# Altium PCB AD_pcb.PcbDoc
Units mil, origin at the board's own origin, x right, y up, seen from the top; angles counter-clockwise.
Board outline 6000 x 2330 mil, 2 copper layers (Top Layer, Bottom Layer); 6 components, 0 nets, 323 pads, 0 vias.
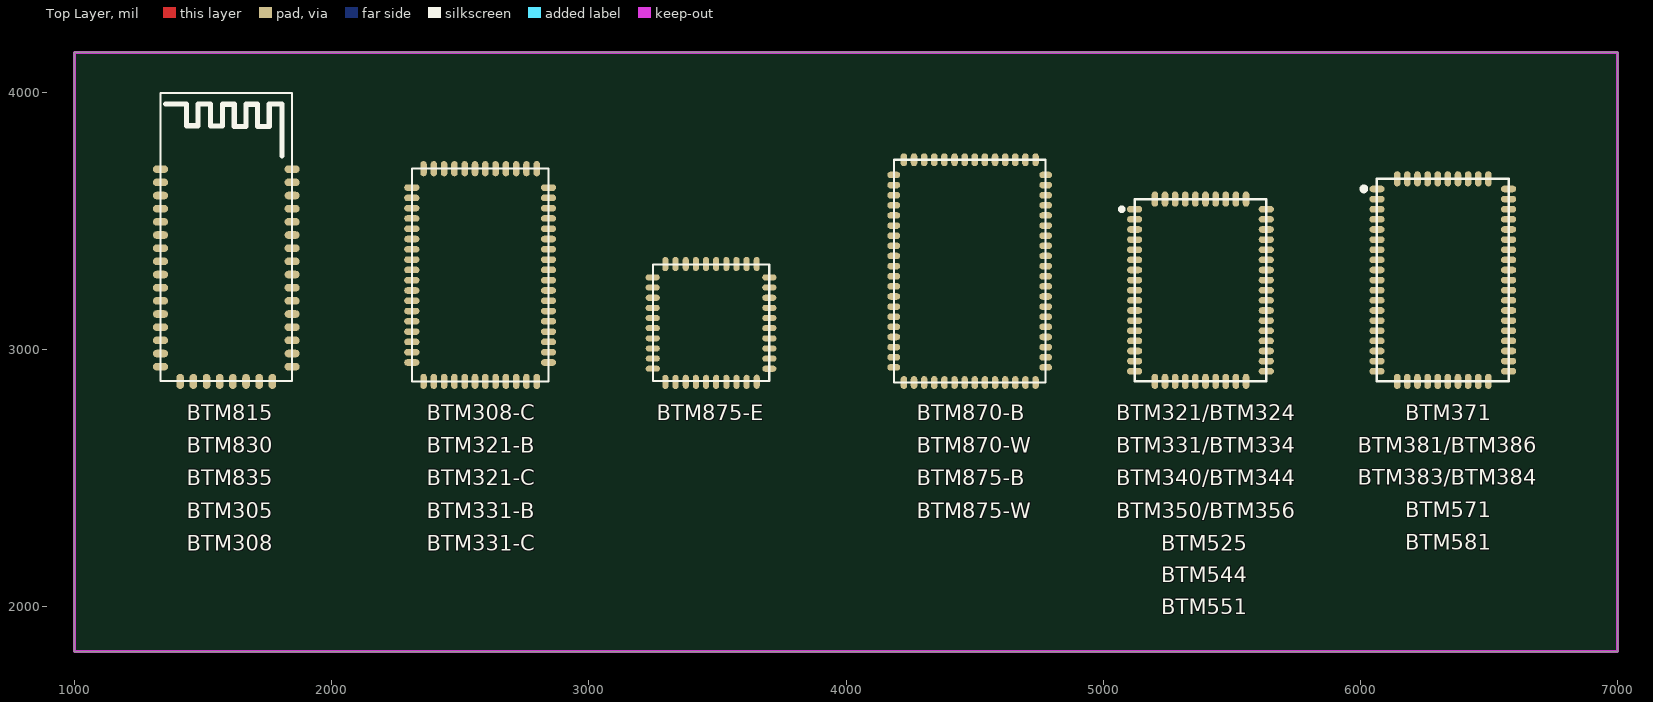
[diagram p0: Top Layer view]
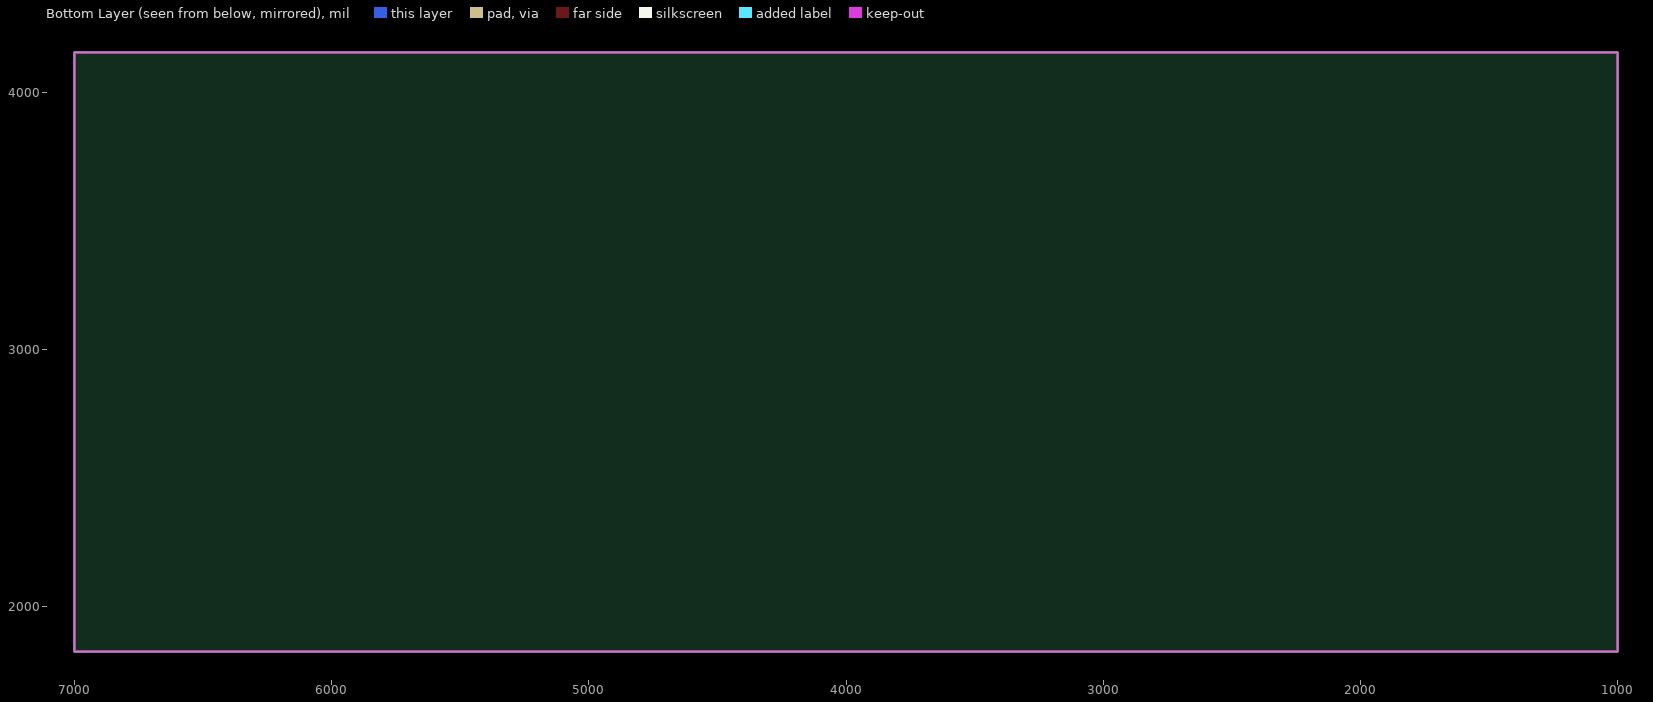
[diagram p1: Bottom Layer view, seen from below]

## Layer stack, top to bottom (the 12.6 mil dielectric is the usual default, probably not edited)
Top Solder: solder mask 0.4, Solder Resist, Dk 3.5
Top Layer: signal copper 1.4
Dielectric 1: dielectric 12.6, FR-4, Dk 4.8
Bottom Layer: signal copper 1.4
Bottom Solder: solder mask 0.4, Solder Resist, Dk 3.5

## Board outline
1000,1825 1000,4155 7000,4155 7000,1825

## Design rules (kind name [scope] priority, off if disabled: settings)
Clearance [All] p1: gap=10
PolygonConnect [All] p1: connectstyle=Relief reliefconductorwidth=10 reliefentries=4 polygonreliefangle="90 Angle" airgapwidth=10
RoutingVias [All] p1: holewidth=28 width=50 viastyle="Through Hole" minholewidth=28 minwidth=50 maxholewidth=28 maxwidth=50
SolderMaskExpansion [All] p1: expansion=4
Width [All] p1: maxlimit=10 minlimit=10 preferedwidth=10
30 further rules are at their usual default settings.

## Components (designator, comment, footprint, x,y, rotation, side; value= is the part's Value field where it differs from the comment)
? "" BTM571 6320,3269.37 r0 top
? "" BTM05F 1590.91,3288.07 r0 top
? "" BTM625-C 2577.74,3289.05 r0 top
? "" BTM875-E 3475.23,3102.89 r0 top
? "" BTM870-B 4480.99,3304.21 r0 top
? "" BTM524 5377.9,3230 r0 top

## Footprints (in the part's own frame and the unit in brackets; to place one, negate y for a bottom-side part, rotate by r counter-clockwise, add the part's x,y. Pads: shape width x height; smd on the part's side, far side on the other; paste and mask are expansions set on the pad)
BTM05F [mm]
  oval 1.5x0.75 smd: 1(-6.5,10.475) 2(-6.5,9.175) 3(-6.5,7.875) 4(-6.5,6.575) 5(-6.5,5.275) 6(-6.5,3.975) 7(-6.5,2.675) 8(-6.5,1.375) 9(-6.5,0.075) 10(-6.5,-1.225) 11(-6.5,-2.525) 12(-6.5,-3.825) 13(-6.5,-5.125) 14(-6.5,-6.425) 15(-6.5,-7.725) 16(-6.5,-9.025) 25(6.5,-9.025) 26(6.5,-7.725) 27(6.5,-6.425) 28(6.5,-5.125) 29(6.5,-3.825) 30(6.5,-2.525) 31(6.5,-1.225) 32(6.5,0.075) 33(6.5,1.375) 34(6.5,2.675) 35(6.5,3.975) 36(6.5,5.275) 37(6.5,6.575) 38(6.5,7.875) 39(6.5,9.175) 40(6.5,10.475)
  oval 0.75x1.5 smd: 17(-4.55,-10.475) 18(-3.25,-10.475) 19(-1.95,-10.475) 20(-0.65,-10.475) 21(0.65,-10.475) 22(1.95,-10.475) 23(3.25,-10.475) 24(4.55,-10.475)
  silkscreen extent -6.51,-10.45 6.49,18, body extent -6.51,-10.45 6.49,18, height 2.6
BTM524 [mm]
  oval 1.5x0.65 smd: 1(-6.5,8) 2(-6.5,7) 3(-6.5,6) 4(-6.5,5) 5(-6.5,4) 6(-6.5,3) 7(-6.5,2) 8(-6.5,1) 9(-6.5,0) 10(-6.5,-1) 11(-6.5,-2) 12(-6.5,-3) 13(-6.5,-4) 14(-6.5,-5) 15(-6.5,-6) 16(-6.5,-7) 17(-6.5,-8) 28(6.5,-8) 29(6.5,-7) 30(6.5,-6) 31(6.5,-5) 32(6.5,-4) 33(6.5,-3) 34(6.5,-2) 35(6.5,-1) 36(6.5,0) 37(6.5,1) 38(6.5,2) 39(6.5,3) 40(6.5,4) 41(6.5,5) 42(6.5,6) 43(6.5,7) 44(6.5,8)
  oval 0.65x1.5 smd: 18(-4.5,-9) 19(-3.5,-9) 20(-2.5,-9) 21(-1.5,-9) 22(-0.5,-9) 23(0.5,-9) 24(1.5,-9) 25(2.5,-9) 26(3.5,-9) 27(4.5,-9) 45(4.5,9) 46(3.5,9) 47(2.5,9) 48(1.5,9) 49(0.5,9) 50(-0.5,9) 51(-1.5,9) 52(-2.5,9) 53(-3.5,9) 54(-4.5,9)
  silkscreen extent -7.9,-9 6.5,9, body extent -6.5,-9 6.5,9, height 2.6
BTM571 [mm]
  oval 1.5x0.65 smd: 1(-6.5,9) 2(-6.5,8) 3(-6.5,7) 4(-6.5,6) 5(-6.5,5) 6(-6.5,4) 7(-6.5,3) 8(-6.5,2) 9(-6.5,1) 10(-6.5,0) 11(-6.5,-1) 12(-6.5,-2) 13(-6.5,-3) 14(-6.5,-4) 15(-6.5,-5) 16(-6.5,-6) 17(-6.5,-7) 18(-6.5,-8) 19(-6.5,-9) 30(6.5,-9) 31(6.5,-8) 32(6.5,-7) 33(6.5,-6) 34(6.5,-5) 35(6.5,-4) 36(6.5,-3) 37(6.5,-2) 38(6.5,-1) 39(6.5,0) 40(6.5,1) 41(6.5,2) 42(6.5,3) 43(6.5,4) 44(6.5,5) 45(6.5,6) 46(6.5,7) 47(6.5,8) 48(6.5,9)
  oval 0.65x1.5 smd: 20(-4.5,-10) 21(-3.5,-10) 22(-2.5,-10) 23(-1.5,-10) 24(-0.5,-10) 25(0.5,-10) 26(1.5,-10) 27(2.5,-10) 28(3.5,-10) 29(4.5,-10) 49(4.5,10) 50(3.5,10) 51(2.5,10) 52(1.5,10) 53(0.5,10) 54(-0.5,10) 55(-1.5,10) 56(-2.5,10) 57(-3.5,10) 58(-4.5,10)
  silkscreen extent -7.98,-10 6.5,10, body extent -6.5,-10 6.5,10, height 2.6
BTM625-C [mm]
  oval 1.5x0.65 smd: 1(-6.75,8.636) 2(-6.75,7.62) 3(-6.75,6.604) 4(-6.75,5.588) 5(-6.75,4.572) 6(-6.75,3.556) 7(-6.75,2.54) 8(-6.75,1.524) 9(-6.75,0.508) 10(-6.75,-0.508) 11(-6.75,-1.524) 12(-6.75,-2.54) 13(-6.75,-3.556) 14(-6.75,-4.572) 15(-6.75,-5.588) 16(-6.75,-6.604) 17(-6.75,-7.62) 18(-6.75,-8.636) 31(6.75,-8.636) 32(6.75,-7.62) 33(6.75,-6.604) 34(6.75,-5.588) 35(6.75,-4.572) 36(6.75,-3.556) 37(6.75,-2.54) 38(6.75,-1.524) 39(6.75,-0.508) 40(6.75,0.508) 41(6.75,1.524) 42(6.75,2.54) 43(6.75,3.556) 44(6.75,4.572) 45(6.75,5.588) 46(6.75,6.604) 47(6.75,7.62) 48(6.75,8.636)
  round 0.8 on Top Overlay: 4(-8.169,8.617)
  oval 0.65x1.5 smd: 19(-5.588,-10.5) 20(-4.572,-10.5) 21(-3.556,-10.5) 22(-2.54,-10.5) 23(-1.524,-10.5) 24(-0.508,-10.5) 25(0.508,-10.5) 26(1.524,-10.5) 27(2.54,-10.5) 28(3.556,-10.5) 29(4.572,-10.5) 30(5.588,-10.5) 49(5.588,10.5) 50(4.572,10.5) 51(3.556,10.5) 52(2.54,10.5) 53(1.524,10.5) 54(0.508,10.5) 55(-0.508,10.5) 56(-1.524,10.5) 57(-2.54,10.5) 58(-3.556,10.5) 59(-4.572,10.5) 60(-5.588,10.5)
  silkscreen extent -6.75,-10.5 6.75,10.5, body extent -6.75,-10.5 6.75,10.5, height 2.6
BTM870-B [mm]
  oval 1.27x0.65 smd: 1(-7.5,9.5) 2(-7.5,8.5) 3(-7.5,7.5) 4(-7.5,6.5) 5(-7.5,5.5) 6(-7.5,4.5) 7(-7.5,3.5) 8(-7.5,2.5) 9(-7.5,1.5) 10(-7.5,0.5) 11(-7.5,-0.5) 12(-7.5,-1.5) 13(-7.5,-2.5) 14(-7.5,-3.5) 15(-7.5,-4.5) 16(-7.5,-5.5) 17(-7.5,-6.5) 18(-7.5,-7.5) 19(-7.5,-8.5) 20(-7.5,-9.5) 35(7.5,-9.5) 36(7.5,-8.5) 37(7.5,-7.5) 38(7.5,-6.5) 39(7.5,-5.5) 40(7.5,-4.5) 41(7.5,-3.5) 42(7.5,-2.5) 43(7.5,-1.5) 44(7.5,-0.5) 45(7.5,0.5) 46(7.5,1.5) 47(7.5,2.5) 48(7.5,3.5) 49(7.5,4.5) 50(7.5,5.5) 51(7.5,6.5) 52(7.5,7.5) 53(7.5,8.5) 54(7.5,9.5)
  round 0.8 on Top Overlay: 6(-8.815,9.492)
  oval 0.65x1.27 smd: 21(-6.499,-11) 22(-5.499,-11) 23(-4.499,-11) 24(-3.499,-11) 25(-2.499,-11) 26(-1.499,-11) 27(-0.499,-11) 28(0.501,-11) 29(1.501,-11) 30(2.501,-11) 31(3.501,-11) 32(4.501,-11) 33(5.501,-11) 34(6.501,-11) 55(6.499,11) 56(5.499,11) 57(4.499,11) 58(3.499,11) 59(2.499,11) 60(1.499,11) 61(0.499,11) 62(-0.501,11) 63(-1.501,11) 64(-2.501,11) 65(-3.501,11) 66(-4.501,11) 67(-5.501,11) 68(-6.501,11)
  silkscreen extent -7.5,-11 7.5,11, body extent -7.5,-11 7.5,11, height 2.6
BTM875-E [mm]
  oval 1.4x0.6 smd: 1(-5.76,4.497) 2(-5.759,3.496) 3(-5.755,2.486) 4(-5.754,1.485) 5(-5.754,0.484) 6(-5.754,-0.517) 7(-5.753,-1.517) 8(-5.753,-2.518) 9(-5.753,-3.519) 10(-5.752,-4.52) 21(5.76,-4.521) 22(5.759,-3.52) 23(5.759,-2.52) 24(5.759,-1.519) 25(5.758,-0.518) 26(5.758,0.483) 27(5.758,1.484) 28(5.757,2.484) 29(5.753,3.494) 30(5.752,4.495)
  round 0.8 on Top Overlay: 7(-7.117,4.487)
  oval 0.6x1.4 smd: 11(-4.503,-5.821) 12(-3.502,-5.821) 13(-2.492,-5.816) 14(-1.491,-5.816) 15(-0.49,-5.816) 16(0.51,-5.815) 17(1.511,-5.815) 18(2.512,-5.815) 19(3.513,-5.814) 20(4.514,-5.814) 31(4.511,5.821) 32(3.51,5.821) 33(2.509,5.821) 34(1.509,5.82) 35(0.508,5.82) 36(-0.493,5.82) 37(-1.494,5.819) 38(-2.495,5.819) 39(-3.505,5.814) 40(-4.505,5.814)
  silkscreen extent -5.75,-5.75 5.75,5.75, body extent -5.75,-5.75 5.75,5.75, height 2.6

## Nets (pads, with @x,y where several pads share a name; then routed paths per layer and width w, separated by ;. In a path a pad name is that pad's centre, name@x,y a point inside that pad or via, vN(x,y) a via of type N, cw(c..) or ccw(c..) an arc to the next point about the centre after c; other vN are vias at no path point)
pads on no net: ?.1 ?.2 ?.3 ?.4 ?.5 ?.6 ?.7 ?.8 ?.9 ?.10 ?.11 ?.12 ?.13 ?.14 ?.15 ?.16 ?.17 ?.18 ?.19 ?.20 ?.21 ?.22 ?.23 ?.24 ?.25 ?.26 ?.27 ?.28 ?.29 ?.30 ?.31 ?.32 ?.33 ?.34 ?.35 ?.36 ?.37 ?.38 ?.39 ?.40 ?.41 ?.42 ?.43 ?.44 ?.45 ?.46 ?.47 ?.48 ?.49 ?.50 ?.51 ?.52 ?.53 ?.54 ?.55 ?.56 ?.57 ?.58 ?.59 ?.60 ?.61 ?.62 ?.63 ?.64 ?.65 ?.66 ?.67 ?.68

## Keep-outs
Keep-Out Layer:
  lines w11.81: 1000,1825 7000,1825 7000,4155 1010,4155 1000,4155 1000,1825

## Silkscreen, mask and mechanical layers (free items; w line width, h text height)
Top Overlay:
  text "BTM815" at 1437.35,2725 h59.06
  text "BTM308-C" at 2370,2725 h59.06
  text "BTM875-E" at 3265,2725 h59.06
  text "BTM870-B" at 4275,2725 h59.06
  text "BTM321/BTM324" at 5050,2725 h59.06
  text "BTM371" at 6175,2725 h59.06
  text "BTM381/BTM386" at 5990,2599.17 h59.06
  text "BTM830" at 1437.35,2598 h59.06
  text "BTM321-B" at 2370,2598 h59.06
  text "BTM870-W" at 4275,2598 h59.06
  text "BTM331/BTM334" at 5050,2598 h59.06
  text "BTM383/BTM384" at 5990,2473.33 h59.06
  text "BTM835" at 1437.35,2471 h59.06
  text "BTM321-C" at 2370,2471 h59.06
  text "BTM875-B" at 4275,2471 h59.06
  text "BTM340/BTM344" at 5050,2471 h59.06
  text "BTM571" at 6175,2347.5 h59.06
  text "BTM305" at 1437.35,2344 h59.06
  text "BTM331-B" at 2370,2344 h59.06
  text "BTM875-W" at 4275,2344 h59.06
  text "BTM350/BTM356" at 5050,2344 h59.06
  text "BTM581" at 6175,2221.67 h59.06
  text "BTM308" at 1437.35,2217 h59.06
  text "BTM331-C" at 2370,2217 h59.06
  text "BTM525" at 5225,2217 h59.06
  text "BTM544" at 5225,2095 h59.06
  text "BTM551" at 5225,1970 h59.06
